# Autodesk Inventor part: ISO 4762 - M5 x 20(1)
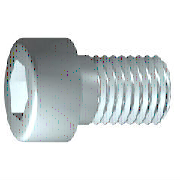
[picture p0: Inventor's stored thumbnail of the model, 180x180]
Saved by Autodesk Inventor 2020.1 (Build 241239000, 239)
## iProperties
Created: 2019-01
Part Number: ISO 4762 - M5 x 20(1)
Material: Edelstahl, 440C
Description: Innensechskantschraube
Document SubType Name: Modeling
Standard: ISO 4762
Designer: lutzd
Standard Revision: Fourth edition 2004-03-01
Standards Organization: ISO
Language: de-DE
Size Designation: M5 x 20
Categories: <MemberInstance><Categories><Category DisplayName="Verbindungselemente" InternalName="e4da775c-781d-43d5-af7c-5136215cf5a6" Mnemonic="FSTN"><Category DisplayNam
Mass: 4.89344 g
Surface Area: 5.88237 cm^2
Volume: 0.631412 cm^3
Density: 7.75 g/cm^3
Appearance: Halbpoliert
IsCustomPart: 0
Author: lutzd
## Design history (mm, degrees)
workplane "Work Plane1"
fillet "Fillet2" dims "d30" = 0.1 (= R)
sketch "Skizze1"
  geometry: L1 (-1.167, 0)-(20, 0); L2 (20, 0)-(20, 2.5); L3 (20, 2.5)-(2, 2.5); L4 (2, 2.5)-(1.509, 2.5); L5 (1.509, 2.5)-(0, 2.5); L6 (0, 2.5)-(0, 4.25); L7 (0, 4.25)-(-5, 4.25); L8 (-5, 4.25)-(-5, 2.309); L9 (-5, 2.309)-(-2.5, 2.309); L10 (-2.5, 2.309)-(-1.167, 0); L11 (-10, 0)-(25, 0) reference; L12 (0, -0.85)-(0, 5.1) reference; L13 (2, 2.5)-(0, 2.5)
  constraints: 22 end point, 6 parallel, 2 collinear, 2 perpendicular, 1 horizontal, 1 point on line
  dimensions: "d1" = 18 distance from line of L3.end L2 (= GEL); "d2" = 0.49086 distance of L4.end L3.end (computed from GAL); "d3" = 5 distance between parallel lines of L8 L6 (= KOH); "d4" = 2.5 distance of L8.end L9.end (= INTI); "d5" = 60 deg angle of L10 L1; "d6" = 5 diameter of L3 L1 (= GD); "d7" = 5 diameter of L5 L1 (= BDM); "d8" = 4.6188 diameter of L9 L1 (= 1.1547 x SW); "d9" = 8.5 diameter of L7 L1 (= KOD); "d26" = 20 distance between parallel lines of L12 L2 (= NLG)
revolve "Körper" sketch "Skizze1" stored, may be unused: angle "d10" = 90 deg
sketch "Skizze2"
  geometry: L1 (0, -5.95)-(0, 5.95) reference; L2 (-5.95, 0)-(5.95, 0) reference; L3 (2.309, 0)-(1.155, -2); L4 (1.155, -2)-(-1.155, -2); L5 (-1.155, -2)-(-2.309, 0); L6 (-2.309, 0)-(-1.155, 2); L7 (-1.155, 2)-(1.155, 2); L8 (1.155, 2)-(2.309, 0); 2 further points
  constraints: 12 end point, 1 coincident, 1 horizontal alignment, 1 point on line, 12 other
extrude "Loch" join sketch "Skizze2" stored distance "d11" = 10; taper "d12" = 0 deg
body "Solid1"
fillet "Rundung1" dims "d17" = 0.5 (= RR)
feature "Gewinde" dims "d13" = 18 (= GEL), "d14" = 0
chamfer "Fase1" distance "d15" = 0.49076 (= -0.5 x SPD + 0.5 x GD); stored, may be unused: second distance "d16" = 0.49076 (= GUL), angle "d27" = 45 deg
other parameters: "GD" = 5 [user parameter; used in 2 equation terms], "NLG" = 20 [user parameter; used in 1 equation term], "GEL" = 18 [user parameter; used in 2 equation terms], "KOD" = 8.5 [user parameter; used in 1 equation term], "KOH" = 5 [user parameter; used in 1 equation term], "INTI" = 2.5 [user parameter; used in 1 equation term], "GAL" = 0.49076 (= 0.61345 x PTC) [user parameter; used in 1 equation term], "GUL" = 0.49076 (= 0.61345 x PTC) [user parameter; used in 1 equation term], "BDM" = 5 (= NND) [user parameter; used in 1 equation term], "SW" = 4 [user parameter; used in 2 equation terms], "RR" = 0.5 [user parameter; used in 1 equation term], "SPD" = 4.01848 (= NND - 1.2269 x PTC) [user parameter; used in 1 equation term], "d19" = 0, "d28" = 0, "d29" = 0, "R" = 0.1 [user parameter; used in 1 equation term], "TOA" = 30 deg [user parameter], "GD1" = 4.01848 (= THREADDIA - 1.2269 x PTC) [user parameter], "THREADDIA" = 5 [user parameter; used in 1 equation term], "FAWI" = 45 deg [user parameter], "TPU" = 12.5 (computed from PTC) [user parameter], "PTC" = 0.8 [user parameter; used in 5 equation terms], "NND" = 5 [user parameter; used in 2 equation terms], "E0" = 4.62 (= 1.155 x SW) [user parameter]
